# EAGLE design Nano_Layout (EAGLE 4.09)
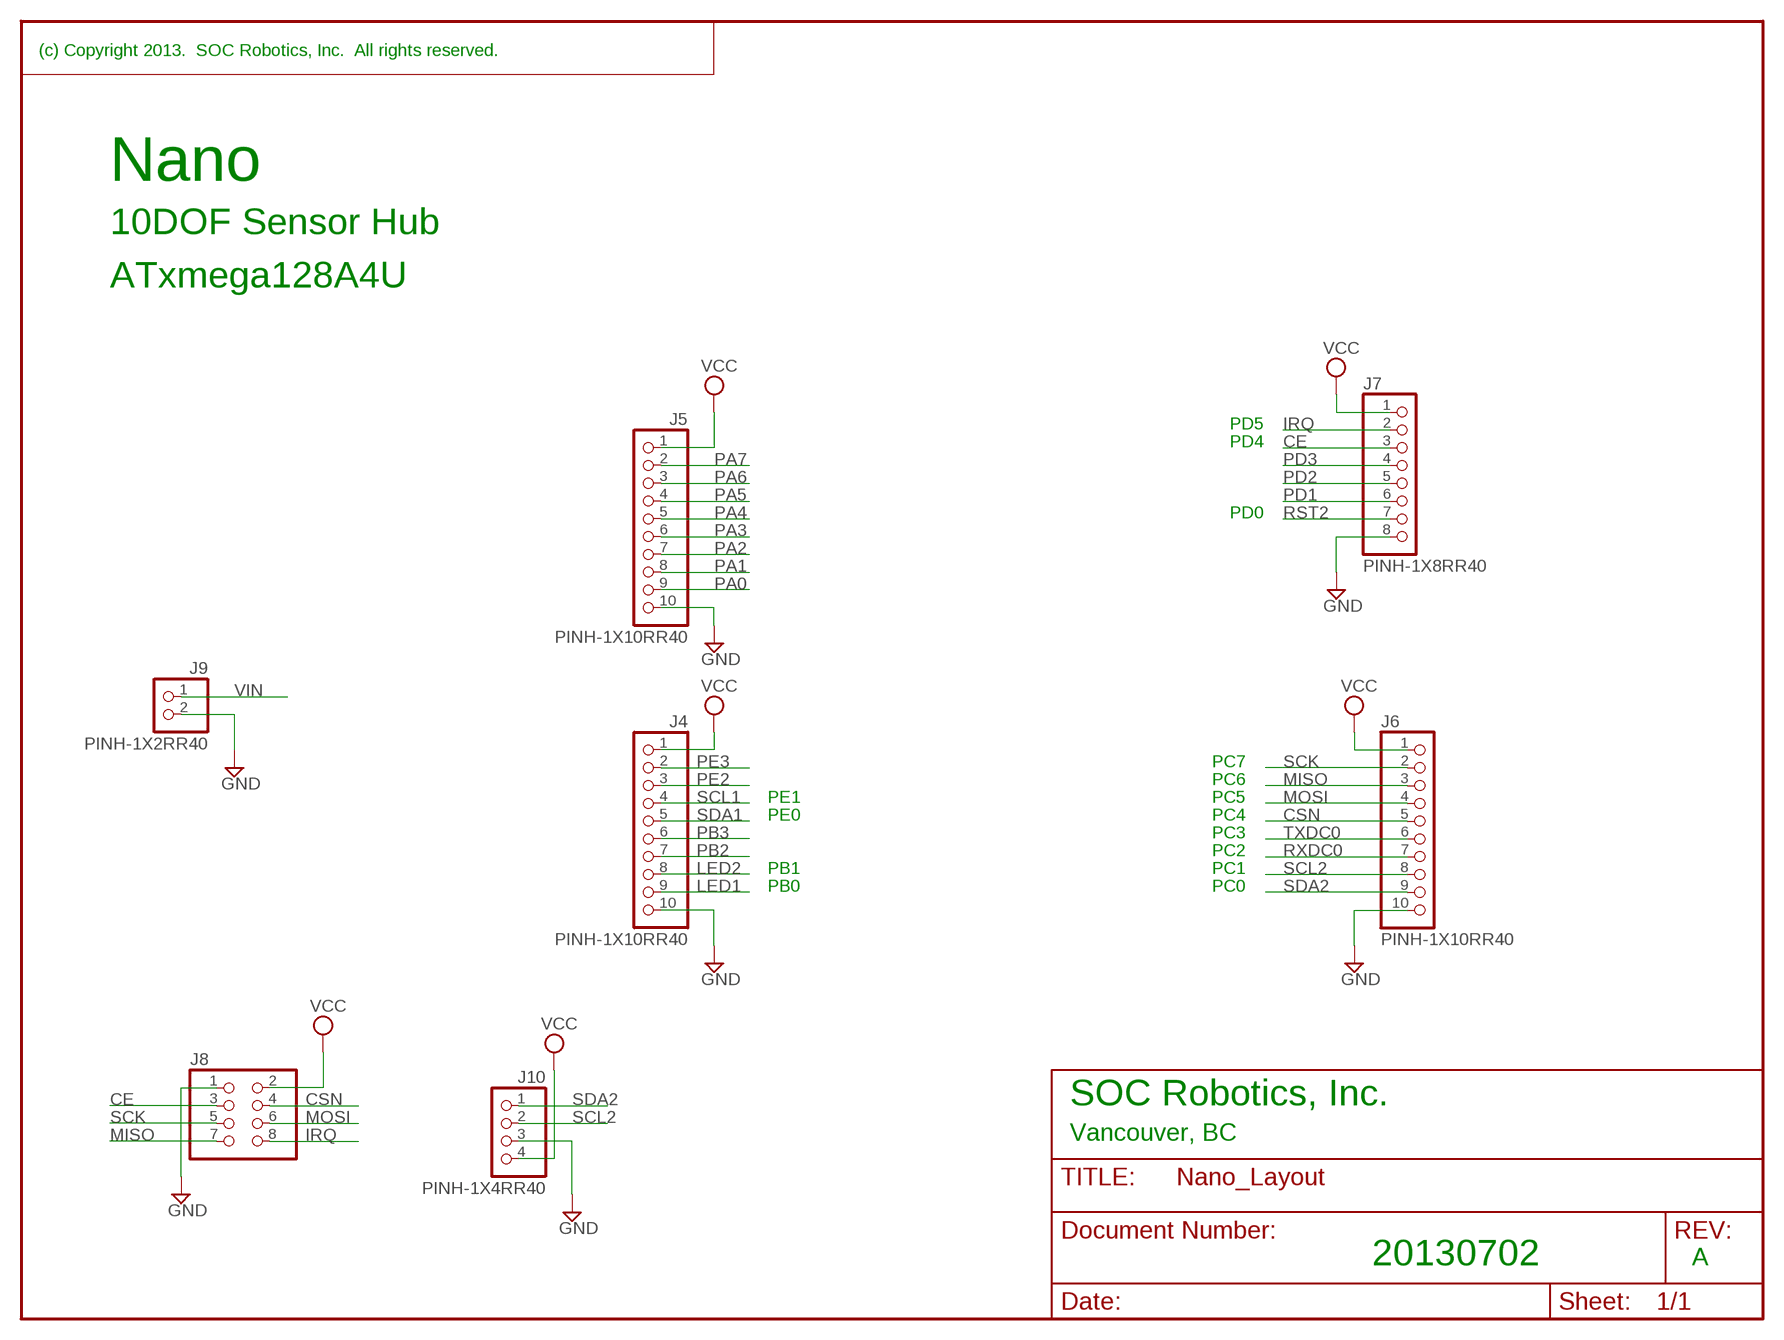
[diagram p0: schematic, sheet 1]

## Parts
J4  PINH-1X10RR40  [1X10ROUND]
J5  PINH-1X10RR40  [1X10ROUND]
J6  PINH-1X10RR40  [1X10ROUND]
J7  PINH-1X8RR40  [1X8ROUND]
J8  PINHD-2X4HEX  [2X04]
J9  PINH-1X2RR40  [1X2ROUND]
J10  PINH-1X4RR40  [1X4ROUND]

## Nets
CE: J7.3 J8.3
CSN: J6.5 J8.4
GND: J4.10 J5.10 J6.10 J7.8 J8.1 J9.2 J10.3
IRQ: J7.2 J8.8
LED1: J4.9
LED2: J4.8
MISO: J6.3 J8.7
MOSI: J6.4 J8.6
PA0: J5.9
PA1: J5.8
PA2: J5.7
PA3: J5.6
PA4: J5.5
PA5: J5.4
PA6: J5.3
PA7: J5.2
PB2: J4.7
PB3: J4.6
PD1: J7.6
PD2: J7.5
PD3: J7.4
PE2: J4.3
PE3: J4.2
RST2: J7.7
RXDC0: J6.7
SCK: J6.2 J8.5
SCL1: J4.4
SCL2: J6.8 J10.2
SDA1: J4.5
SDA2: J6.9 J10.1
TXDC0: J6.6
VCC: J4.1 J5.1 J6.1 J7.1 J8.2 J10.4
VIN: J9.1

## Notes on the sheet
- (c) Copyright 2013.  SOC Robotics, Inc.  All rights reserved.
- Nano
- 10DOF Sensor Hub
- ATxmega128A4U
- PD5
- PD4
- PD0
- PC7
- PC6
- PE1 | PC5
- PE0 | PC4
- PC3
- PC2
- PB1 | PC1
- PB0 | PC0
- SOC Robotics, Inc.
- Vancouver, BC
- 20130702 | A

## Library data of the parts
J4-J6 = pinhead:PINH-1X10R
J7 = pinhead:PINH-1X8R
J8 = pinhead:PINHD-2X4: PIN HEADER
J9 = pinhead:PINH-1X2R: 1x2 Pin head round
J10 = pinhead:PINH-1X4R: 1x4 Pin Head Round

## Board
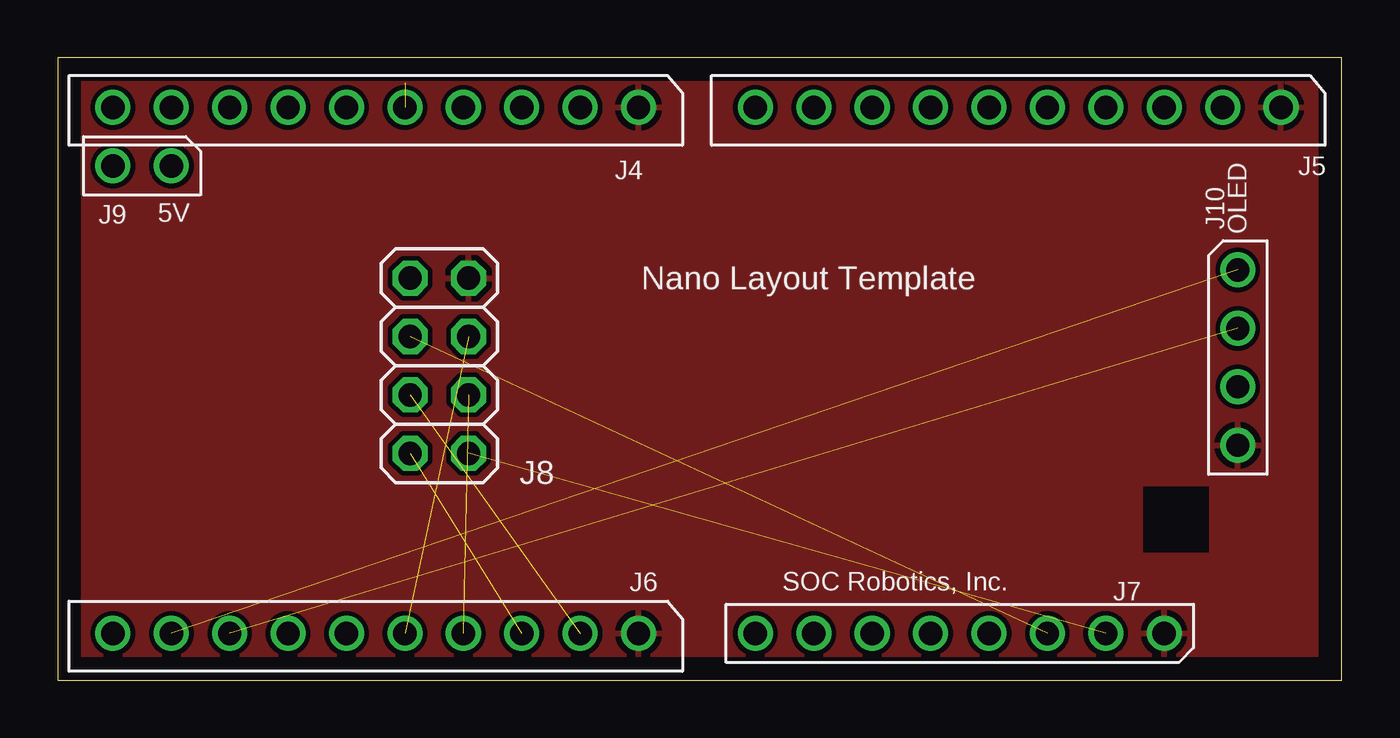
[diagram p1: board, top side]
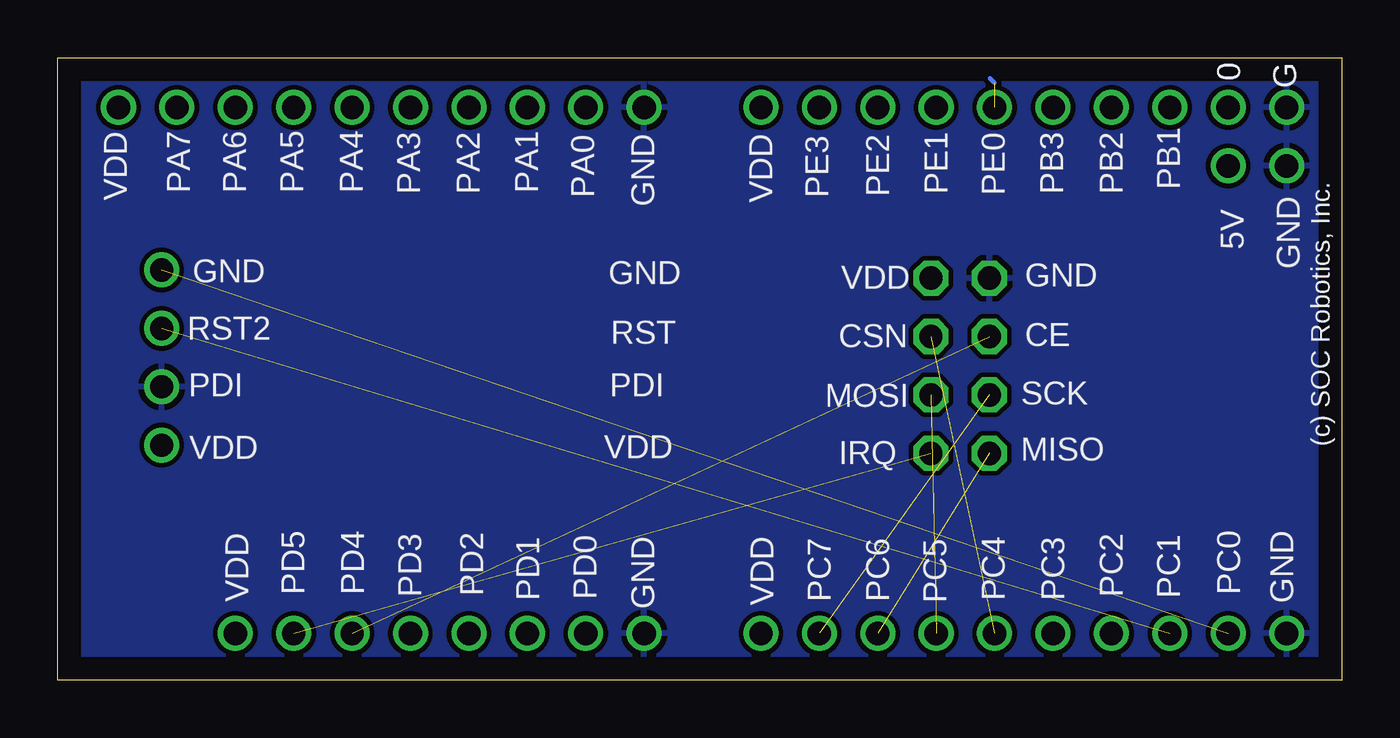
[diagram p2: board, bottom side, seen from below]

Size 55.86 x 27.08 mm. Coordinates in mm from the lower left corner, seen from the top.
Outline: 0,0 55.86,0 55.86,27.08 0,27.08 0,0
Copper layers used: Top, Bottom
tRestrict: area 47.2,5.6 to 50.1,8.4

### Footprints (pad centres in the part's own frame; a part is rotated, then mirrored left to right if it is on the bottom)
1X10ROUND = drill 1.016 round: 1 -11.43,0; 2 -8.89,0; 3 -6.35,0; 4 -3.81,0; 5 -1.27,0; 6 1.27,0; 7 3.81,0; 8 6.35,0; 9 8.89,0; 10 11.43,0
1X8ROUND = drill 1.016 round: 1 -8.89,0; 2 -6.35,0; 3 -3.81,0; 4 -1.27,0; 5 1.27,0; 6 3.81,0; 7 6.35,0; 8 8.89,0
2X04 = drill 1.016 octagon: 1 -3.81,-1.27; 2 -3.81,1.27; 3 -1.27,-1.27; 4 -1.27,1.27; 5 1.27,-1.27; 6 1.27,1.27; 7 3.81,-1.27; 8 3.81,1.27
1X2ROUND = drill 1.016 round: 1 -1.27,0; 2 1.27,0
1X4ROUND = drill 1.016 round: 1 -3.81,0; 2 -1.27,0; 3 1.27,0; 4 3.81,0

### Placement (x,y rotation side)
J4  13.84,24.9 180 top
J5  41.78,24.9 180 top
J6  13.84,2.04 180 top
J7  39.24,2.04 180 top
J8  16.61,13.68 270 top
J9  3.68,22.36 180 top
J10  51.33,14.03 270 top

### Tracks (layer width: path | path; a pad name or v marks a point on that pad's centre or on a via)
CE  (1 unrouted)
CSN  (1 unrouted)
GND
  pour Bottom: 0.12,26.96 55.75,26.96 55.75,0.11 0.12,0.11
IRQ  (1 unrouted)
MISO  (1 unrouted)
MOSI  (1 unrouted)
SCK  (1 unrouted)
SCL2  (1 unrouted)
SDA1  (1 unrouted)
  Bottom 0.203: 15.11,25.97 15.31,26.17
SDA2  (1 unrouted)
VCC
  pour Top: 0.12,26.96 55.75,26.96 55.75,0.11 0.12,0.11

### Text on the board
tPlace: 5V | OLED | Nano Layout Template | SOC Robotics, Inc.
bPlace: G | 0 | PB1 | PB2 | PB3 | PE0 | PE1 | PE2 | PE3 | VDD | GND | PA0 | PA1 | PA2 | PA3 | PA4 | PA5 | PA6 | PA7 | VDD | (c) SOC Robotics, Inc. | GND | 5V | GND | VDD | GND | GND | CE | RST | RST2 | CSN | SCK | MOSI | PDI | PDI | MISO | VDD | VDD | IRQ | GND | PC0 | PD4 | PD5 | PC1 | PC2 | PC3 | PC4 | PC5 | PC6 | PC7 | VDD | GND | PD0 | PD1 | PD2 | PD3 | VDD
